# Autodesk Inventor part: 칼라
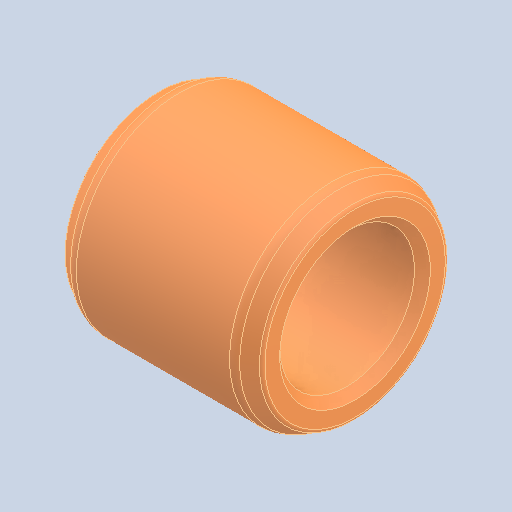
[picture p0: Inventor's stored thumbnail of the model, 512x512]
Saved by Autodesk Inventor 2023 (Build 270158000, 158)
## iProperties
Created: 2025-03
Part Number: 칼라
Material: 강철, 연강
Document SubType Name: Modeling
Designer: ADMIN_PC
Density: 7.86 g/cm^3
Appearance: 기본값
Author: jhkim
Sending System: Autodesk Inventor 2025
Preprocessor: ST-DEVELOPER v20
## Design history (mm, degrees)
feature "솔리드1"
node "솔리드2"
